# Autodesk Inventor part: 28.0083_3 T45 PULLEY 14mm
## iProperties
Created: 2006-12
Document SubType Name: Modeling
Designer: Andy Moles
Material: Aluminum-6061
Part Number: 28.0083_3 T45 PULLEY 14mm
Density: 2.71 g/cm^3
Author: Andy Moles
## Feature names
1. Extrusion1
2. Extrusion3
3. Extrusion4
4. Mirror1
5. Extrusion5
6. Chamfer1
